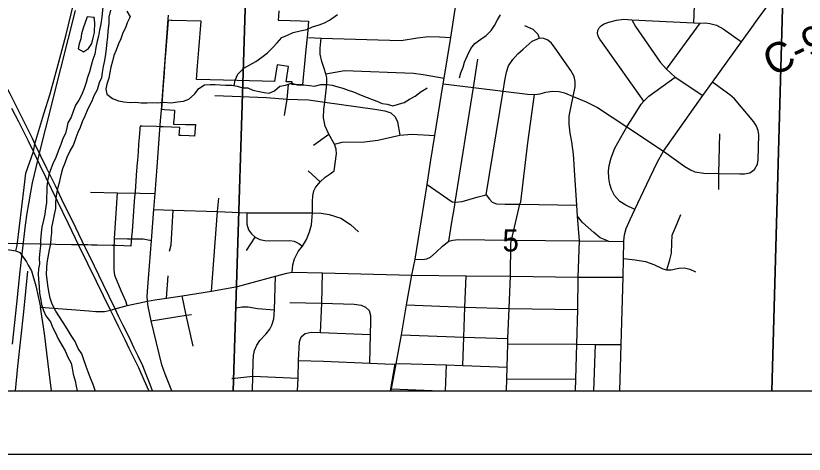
# Model space of a CAD drawing. Extents: x 0 to 34, y 0 to 22.
# Drawn here: x 3.672 to 5.169, y 14 to 14.832 of the extents above; entities that cross this region are included whole.
import ezdxf

# ---------------------------------------------------------------- set-up
doc = ezdxf.new("R2010")
doc.units = 0
for name, color, linetype in [('GM_X_City_Street', 7, 'Continuous'), ('GM_X_Corporation', 7, 'Continuous'), ('GM_X_County_Road', 7, 'Continuous'), ('GM_X_County_Road_Text', 7, 'Continuous'), ('GM_X_Major_River', 7, 'Continuous'), ('GM_X_Minor_Lake', 7, 'Continuous'), ('GM_X_Minor_River', 7, 'Continuous'), ('GM_X_Rail_Line', 7, 'Continuous'), ('GM_X_Section_Text', 7, 'Continuous'), ('GM_X_State_Route', 7, 'Continuous'), ('GM_X_Township_Road', 7, 'Continuous'), ('SH_Data', 7, 'Continuous')]:
    doc.layers.add(name, color=color, linetype=linetype)

msp = doc.modelspace()

# ---------------------------------------------------------------- linework, layer by layer
at = {"layer": 'GM_X_City_Street'}
for p, q in [((4.9075, 14.7307), (4.9715, 14.8177)), ((4.2372, 14.5865), (4.2662, 14.6072)), ((4.2274, 14.5376), (4.25, 14.517)), ((3.9083, 14.4952), (3.9365, 14.4945)), ((4.11, 14.3863), (4.1265, 14.4121)), ((3.9584, 14.2959), (3.9613, 14.3388)), ((4.2508, 14.2308), (4.3456, 14.2274)), ((4.7698, 14.1204), (4.7725, 14.2085)), ((4.4878, 14.1204), (4.4895, 14.1694)), ((4.6045, 14.1431), (4.7352, 14.1422)), ((4.3855, 14.1241), (4.4787, 14.1204))]:
    msp.add_line(p, q, dxfattribs=at)
for points in [[(4.9593, 14.8182), (4.9617, 14.8842), (4.9629, 14.9171), (4.9647, 14.9512)], [(4.7769, 14.8042), (4.7796, 14.8087), (4.7839, 14.8132), (4.7889, 14.8163), (4.798, 14.82), (4.8124, 14.8233), (4.8264, 14.8252), (4.8414, 14.8244), (4.9593, 14.8182), (4.9715, 14.8177), (4.9816, 14.8184), (4.9899, 14.8175), (5.0026, 14.8142), (5.0151, 14.8073), (5.0497, 14.7822)], [(4.8414, 14.8244), (4.8485, 14.8114), (4.8955, 14.7439), (4.9075, 14.7307), (4.9239, 14.7154), (4.9766, 14.6804)], [(4.6381, 14.8133), (4.6535, 14.8065), (4.6631, 14.797), (4.6658, 14.7895)], [(4.228, 14.7907), (4.2521, 14.7892), (4.4038, 14.7851), (4.4349, 14.7898), (4.4556, 14.7923), (4.4762, 14.7919), (4.4978, 14.7908)], [(4.8647, 14.67), (4.7889, 14.7762), (4.781, 14.7876), (4.7776, 14.7934), (4.7762, 14.7986), (4.7769, 14.8042)], [(4.2766, 14.5375), (4.2811, 14.57), (4.2806, 14.5786), (4.2774, 14.5884), (4.2662, 14.6072), (4.2597, 14.6222), (4.2562, 14.6382), (4.2569, 14.6549), (4.2586, 14.6679), (4.2625, 14.7024), (4.2625, 14.7139), (4.2609, 14.722), (4.2578, 14.732), (4.2528, 14.7453), (4.2501, 14.7589), (4.2501, 14.7706), (4.2521, 14.7892)], [(4.565, 14.4919), (4.5975, 14.6889), (4.6006, 14.7089), (4.6037, 14.7249), (4.6078, 14.737), (4.6159, 14.7489), (4.6253, 14.7598), (4.6353, 14.7686), (4.6525, 14.7835), (4.6658, 14.7895)], [(4.7347, 14.1204), (4.7352, 14.1422), (4.7374, 14.209), (4.739, 14.2747), (4.74, 14.3362), (4.7421, 14.4049), (4.7387, 14.4516), (4.7374, 14.4723), (4.7337, 14.5292), (4.731, 14.5695), (4.7277, 14.5926), (4.7246, 14.6093), (4.7224, 14.6262), (4.7224, 14.6411), (4.7262, 14.6602), (4.7304, 14.6784), (4.734, 14.6973), (4.7342, 14.7072), (4.7321, 14.7169), (4.7259, 14.7283), (4.6963, 14.7704), (4.6889, 14.78), (4.6823, 14.7856), (4.6748, 14.7885), (4.6658, 14.7895)], [(4.5048, 14.4689), (4.5063, 14.4781), (4.5413, 14.6958), (4.5495, 14.7495)], [(4.2609, 14.722), (4.296, 14.7278), (4.4273, 14.7228), (4.4455, 14.7202), (4.4851, 14.7132)], [(4.8474, 14.4644), (4.83, 14.4724), (4.8188, 14.4796), (4.8088, 14.4909), (4.8033, 14.502), (4.8001, 14.5123), (4.798, 14.5241), (4.7976, 14.5372), (4.7986, 14.5478), (4.8024, 14.5623), (4.8094, 14.581), (4.8324, 14.6211), (4.8451, 14.6409), (4.8592, 14.6639), (4.8647, 14.67), (4.8741, 14.6791), (4.9239, 14.7154)], [(4.1823, 14.6428), (4.187, 14.6738), (4.1899, 14.7015)], [(4.4835, 14.7027), (4.5413, 14.6958), (4.5975, 14.6889), (4.6435, 14.6831), (4.6568, 14.6827), (4.6667, 14.6836), (4.6785, 14.6868), (4.6912, 14.6886), (4.7035, 14.6884), (4.714, 14.6858), (4.7304, 14.6784), (4.7551, 14.6686), (4.7766, 14.6581), (4.8324, 14.6211), (4.9019, 14.575)], [(4.9019, 14.575), (4.9425, 14.5459), (4.9528, 14.5394), (4.9615, 14.5356), (4.9781, 14.5332), (5.0071, 14.5327), (5.0468, 14.532), (5.0555, 14.5317), (5.0656, 14.5338), (5.0747, 14.5405), (5.0803, 14.5505), (5.0812, 14.5588), (5.0826, 14.6058), (5.0817, 14.6141), (5.0784, 14.6225), (5.0732, 14.6304), (5.0365, 14.674), (5.0279, 14.6818), (5.0091, 14.695), (4.9945, 14.7056)], [(4.0501, 14.6803), (4.148, 14.6767), (4.187, 14.6738), (4.2277, 14.6724), (4.2586, 14.6679), (4.3539, 14.6545), (4.3725, 14.6518), (4.3839, 14.6478), (4.3926, 14.6404), (4.3966, 14.6308), (4.4009, 14.6054)], [(4.6034, 14.1204), (4.6045, 14.1431), (4.6051, 14.1652), (4.606, 14.2098), (4.6063, 14.2197), (4.6088, 14.2764), (4.611, 14.3378), (4.6122, 14.4002), (4.6131, 14.4062), (4.6292, 14.4742), (4.6307, 14.4791), (4.6444, 14.5911), (4.6568, 14.6827)], [(4.2774, 14.5884), (4.2914, 14.5922), (4.3341, 14.5927), (4.3594, 14.5958), (4.4009, 14.6054), (4.4238, 14.6074), (4.4678, 14.605)], [(5.0067, 14.5026), (5.0071, 14.5327), (5.0088, 14.6082)], [(4.1967, 14.3453), (4.198, 14.3591), (4.2011, 14.3706), (4.2083, 14.3847), (4.2165, 14.3949), (4.2237, 14.4073), (4.2299, 14.4219), (4.2334, 14.4352), (4.2351, 14.4578), (4.2354, 14.4792), (4.236, 14.49), (4.2381, 14.4995), (4.2413, 14.5059), (4.25, 14.517), (4.2597, 14.5254), (4.2691, 14.5317), (4.2766, 14.5375)], [(4.4529, 14.5117), (4.5006, 14.4789), (4.5063, 14.4781), (4.5193, 14.4797), (4.5502, 14.4882), (4.565, 14.4919), (4.5715, 14.4841), (4.5765, 14.4781), (4.5848, 14.4749), (4.6012, 14.4742), (4.6292, 14.4742), (4.7374, 14.4723)], [(4.0437, 14.3097), (4.055, 14.4605), (4.0574, 14.4859)], [(3.934, 14.4641), (3.9711, 14.463), (4.055, 14.4605), (4.1106, 14.4583), (4.2351, 14.4578), (4.2521, 14.4574), (4.2671, 14.4549), (4.2891, 14.4476), (4.3076, 14.4361), (4.3229, 14.4221)], [(3.964, 14.385), (3.9669, 14.3974), (3.9711, 14.463)], [(4.43, 14.37), (4.4439, 14.3698), (4.4524, 14.3707), (4.4595, 14.3738), (4.47, 14.3834), (4.4821, 14.3947), (4.4945, 14.4041), (4.5002, 14.4402), (4.5048, 14.4689)], [(4.1106, 14.4583), (4.1106, 14.4367), (4.1137, 14.426), (4.1194, 14.4179), (4.1265, 14.4121), (4.1355, 14.4075), (4.1452, 14.4056), (4.154, 14.4051), (4.1922, 14.4053), (4.2007, 14.4041), (4.2093, 14.3998), (4.2165, 14.3949)], [(4.7971, 14.4043), (4.7816, 14.4105), (4.7694, 14.4207), (4.7479, 14.4397), (4.7387, 14.4516)], [(4.9083, 14.3498), (4.9139, 14.3688), (4.9167, 14.3813), (4.9174, 14.4003), (4.9184, 14.4157), (4.9279, 14.4375), (4.9346, 14.4547)], [(3.8839, 14.4089), (3.8992, 14.409), (3.9141, 14.4084), (3.9296, 14.4054)], [(4.4945, 14.4041), (4.5018, 14.4064), (4.5122, 14.4073), (4.6131, 14.4062), (4.7421, 14.4049), (4.7971, 14.4043), (4.8264, 14.4038)], [(3.8833, 14.2823), (3.8812, 14.2905), (3.8724, 14.3099), (3.8598, 14.3389), (3.8586, 14.3497), (3.8587, 14.3715), (3.8587, 14.3889)], [(4.8257, 14.3711), (4.8482, 14.3689), (4.8673, 14.366), (4.8836, 14.3603), (4.9003, 14.3516), (4.9074, 14.35)], [(4.207, 14.1204), (4.2079, 14.1445), (4.2091, 14.1777), (4.2108, 14.2136), (4.2137, 14.2225), (4.2217, 14.2293), (4.2331, 14.2318), (4.2508, 14.2308), (4.2532, 14.2865), (4.2544, 14.3439)], [(4.9074, 14.35), (4.9083, 14.3498), (4.9163, 14.3497), (4.9309, 14.3532), (4.9414, 14.3535), (4.9516, 14.3511), (4.9625, 14.3461)], [(4.1212, 14.1204), (4.122, 14.1479), (4.1229, 14.1752), (4.1235, 14.1872), (4.1253, 14.1966), (4.1299, 14.2067), (4.1356, 14.216), (4.1476, 14.2286), (4.1543, 14.2375), (4.1582, 14.2451), (4.1619, 14.2568), (4.1634, 14.2739), (4.1652, 14.3381)], [(4.5208, 14.1682), (4.5228, 14.2223), (4.5249, 14.2793), (4.5269, 14.3387)], [(4.0088, 14.2048), (3.9955, 14.2638), (3.9877, 14.3007)], [(4.1926, 14.288), (4.2532, 14.2865), (4.3148, 14.2846), (4.3276, 14.2829), (4.3363, 14.279), (4.3434, 14.272)], [(4.4141, 14.2835), (4.5249, 14.2793), (4.6088, 14.2764), (4.739, 14.2747)], [(3.7399, 14.1204), (3.7335, 14.1715), (3.7263, 14.229), (3.7187, 14.2791)], [(4.0896, 14.2778), (4.1021, 14.2794), (4.1134, 14.2794), (4.1308, 14.2768), (4.1634, 14.2739)], [(4.3442, 14.1726), (4.3456, 14.2274), (4.3463, 14.2519), (4.3463, 14.2625), (4.3434, 14.272)], [(3.9292, 14.2534), (3.9955, 14.2638), (4.0055, 14.2652)], [(4.4043, 14.2266), (4.5228, 14.2223), (4.6063, 14.2197)], [(4.606, 14.2098), (4.7374, 14.209), (4.7725, 14.2085), (4.8213, 14.208)], [(4.2091, 14.1777), (4.2561, 14.1767), (4.3442, 14.1726), (4.3871, 14.171), (4.3943, 14.1713), (4.4005, 14.1723), (4.4895, 14.1694), (4.5208, 14.1682), (4.6051, 14.1652)], [(4.0825, 14.1439), (4.122, 14.1479), (4.2079, 14.1445)]]:
    msp.add_lwpolyline(points, dxfattribs=at)
at = {"layer": 'GM_X_Corporation'}
for points in [[(7.1023, 20.9204), (2.837, 20.9204), (2.837, 14.1204), (9.637, 14.1204), (9.637, 20.9204), (9.4036, 20.9204), (9.4022, 20.8667), (9.2273, 20.8723), (9.1354, 20.8749), (9.124, 20.8753), (8.9858, 20.878), (8.9676, 20.8785), (8.8663, 20.881), (8.6259, 20.8892), (8.5535, 20.8914), (8.5421, 20.8915), (8.4667, 20.8934), (8.0602, 20.9055), (7.9522, 20.9084), (7.1104, 20.9188)], [(3.0463, 14.1204), (4.0849, 14.1204), (4.1106, 14.9455), (3.0765, 14.9841)], [(4.0849, 14.1204), (5.1073, 14.1204), (5.1298, 14.9148), (4.1106, 14.9455)], [(5.1073, 14.1204), (6.1556, 14.1204), (6.1854, 14.88), (5.1298, 14.9148)]]:
    msp.add_lwpolyline(points, close=True, dxfattribs=at)
for points in [[(4.1717, 14.8414), (4.1707, 14.8309), (4.17, 14.8234), (4.1927, 14.8227), (4.2123, 14.8222), (4.2279, 14.8217), (4.2256, 14.7971), (4.225, 14.7915), (4.2245, 14.7858), (4.2221, 14.7614), (4.2201, 14.7405), (4.2182, 14.7216), (4.2162, 14.7009), (4.1962, 14.7015), (4.1969, 14.7064), (4.1855, 14.7067), (4.1896, 14.7357), (4.168, 14.7389), (4.1633, 14.7073), (4.0925, 14.7092), (4.0153, 14.7112), (4.0173, 14.737), (4.0196, 14.7672), (4.0238, 14.8214), (3.9688, 14.823), (3.9681, 14.8231), (3.967, 14.8231), (3.9613, 14.8233), (3.957, 14.7675), (3.9559, 14.7533), (3.9547, 14.737), (3.9536, 14.7228), (3.9525, 14.7087), (3.9505, 14.6834), (3.9505, 14.6826), (3.9484, 14.6548), (3.9483, 14.6544), (3.9546, 14.6539), (3.9734, 14.6525), (3.9733, 14.6509), (3.9726, 14.6414), (3.9718, 14.632), (3.9717, 14.6307), (3.9714, 14.6263), (3.9941, 14.6258), (4.0131, 14.6253), (4.0114, 14.6037), (4.0014, 14.6041), (3.9859, 14.6046), (3.9825, 14.6047), (3.9837, 14.6202), (3.952, 14.6212), (3.9458, 14.6214), (3.9395, 14.6216), (3.9117, 14.6226), (3.9079, 14.6227), (3.9076, 14.6193), (3.9074, 14.6165), (3.9062, 14.6008), (3.9053, 14.5885), (3.9041, 14.5733), (3.903, 14.5582), (3.9021, 14.5465), (3.902, 14.5455), (3.9008, 14.5295), (3.9007, 14.5283), (3.9, 14.5189), (3.8984, 14.4978), (3.8981, 14.494), (3.8971, 14.4801), (3.8964, 14.4705), (3.8956, 14.461), (3.8949, 14.4515), (3.8942, 14.442), (3.8935, 14.4325), (3.8928, 14.423), (3.892, 14.4128), (3.8917, 14.409), (3.8914, 14.4052), (3.8906, 14.3949), (3.8773, 14.3953), (3.8629, 14.3958), (3.8591, 14.3959), (3.8553, 14.396), (3.8268, 14.3968), (3.8256, 14.3969), (3.8235, 14.3969), (3.8159, 14.397), (3.8091, 14.3971), (3.797, 14.3973), (3.7868, 14.3972), (3.7781, 14.3976), (3.6263, 14.4007)], [(3.0474, 14.1204), (9.2101, 14.1204)], [(3.4295, 14.1204), (5.4145, 14.1204)]]:
    msp.add_lwpolyline(points, dxfattribs=at)
at = {"layer": 'GM_X_County_Road'}
for points in [[(4.1141, 14.324), (4.1652, 14.3381), (4.1869, 14.3437), (4.1967, 14.3453), (4.2544, 14.3439), (4.4238, 14.3398)], [(4.4238, 14.3398), (4.5269, 14.3387), (4.611, 14.3378), (4.74, 14.3362), (4.8253, 14.3358)], [(3.9221, 14.2907), (3.9363, 14.2927), (3.9584, 14.2959), (3.9877, 14.3007), (4.0437, 14.3097), (4.0932, 14.3183), (4.1141, 14.324)], [(3.8608, 14.276), (3.8833, 14.2823), (3.9221, 14.2907)], [(3.9684, 14.1204), (3.9558, 14.1518), (3.9496, 14.1699), (3.9394, 14.2113), (3.9292, 14.2534), (3.9231, 14.2801), (3.9221, 14.2907)], [(3.7187, 14.2791), (3.7943, 14.2733), (3.8108, 14.272)], [(3.8108, 14.272), (3.8242, 14.2709), (3.8407, 14.2709), (3.8516, 14.2732), (3.8608, 14.276)]]:
    msp.add_lwpolyline(points, dxfattribs=at)
at = {"layer": 'GM_X_Major_River'}
for points in [[(3.8374, 14.8489), (3.8353, 14.8292), (3.8334, 14.8167), (3.8312, 14.8045), (3.8294, 14.7931), (3.8267, 14.7836), (3.8241, 14.7718), (3.8219, 14.7593), (3.8182, 14.7487), (3.8152, 14.7376), (3.8122, 14.7255), (3.8085, 14.7148), (3.8059, 14.7053), (3.8018, 14.6936), (3.7969, 14.6814), (3.7916, 14.6719), (3.7856, 14.662), (3.7811, 14.6502), (3.777, 14.6396), (3.771, 14.6289), (3.7687, 14.619), (3.7665, 14.6088), (3.7612, 14.5989), (3.7575, 14.5879), (3.7523, 14.5749), (3.7478, 14.5631), (3.7421, 14.551), (3.738, 14.5396), (3.7346, 14.5301), (3.7324, 14.5183), (3.7313, 14.5073), (3.731, 14.4978), (3.7303, 14.4879), (3.7303, 14.4773), (3.7285, 14.4663), (3.7274, 14.4556), (3.7248, 14.4442), (3.7218, 14.4306), (3.72, 14.4199), (3.7189, 14.4059), (3.719, 14.3956), (3.7175, 14.3854), (3.7164, 14.3721), (3.7168, 14.3615), (3.7154, 14.352), (3.7147, 14.3417), (3.7151, 14.3322), (3.7163, 14.3178), (3.7171, 14.3057), (3.719, 14.2962), (3.7206, 14.2844), (3.7248, 14.273), (3.7291, 14.2628), (3.7382, 14.2511), (3.7417, 14.2412), (3.7474, 14.2302), (3.7528, 14.2189), (3.7596, 14.2071), (3.7658, 14.1961), (3.7711, 14.184), (3.7769, 14.1726), (3.7788, 14.1632), (3.7811, 14.1522), (3.785, 14.1393), (3.7865, 14.129), (3.7889, 14.1204)], [(3.8313, 14.705), (3.8354, 14.7149), (3.8369, 14.7244), (3.8387, 14.7358), (3.8409, 14.7472), (3.8428, 14.759), (3.8443, 14.7696), (3.8457, 14.7818), (3.8468, 14.792), (3.8475, 14.8027), (3.8493, 14.8171), (3.8493, 14.8289), (3.8523, 14.8422)], [(3.8234, 14.1204), (3.823, 14.1212), (3.8191, 14.1322), (3.8138, 14.1443), (3.8095, 14.1564), (3.8057, 14.1667), (3.8003, 14.1811), (3.7973, 14.1906), (3.7908, 14.2004), (3.785, 14.2137), (3.777, 14.2254), (3.7697, 14.2379), (3.7617, 14.25), (3.7548, 14.2606), (3.7483, 14.2716), (3.7411, 14.2845), (3.7376, 14.2959), (3.7345, 14.3091), (3.733, 14.3209), (3.7306, 14.3414), (3.7309, 14.3535), (3.7316, 14.363), (3.7335, 14.3737), (3.7361, 14.3877), (3.7383, 14.3991), (3.7394, 14.4101), (3.7405, 14.4204), (3.7408, 14.4303), (3.743, 14.4424), (3.7456, 14.4549), (3.7478, 14.466), (3.7482, 14.4755), (3.7489, 14.4865), (3.7503, 14.4971), (3.7526, 14.507), (3.7556, 14.5184), (3.7582, 14.5298), (3.7615, 14.5419), (3.766, 14.553), (3.7694, 14.5636), (3.7746, 14.5743), (3.7814, 14.5864), (3.7866, 14.6009), (3.7908, 14.6111), (3.7949, 14.6206), (3.7986, 14.6313), (3.8039, 14.6419), (3.8095, 14.656), (3.817, 14.6708), (3.8208, 14.6803), (3.8272, 14.6921), (3.8313, 14.705)]]:
    msp.add_lwpolyline(points, dxfattribs=at)
at = {"layer": 'GM_X_Minor_Lake'}
for points in [[(3.8076, 14.8298), (3.8038, 14.8188), (3.8001, 14.8082), (3.7971, 14.7979), (3.7953, 14.788), (3.7926, 14.7785), (3.7908, 14.7691), (3.8003, 14.7634), (3.8101, 14.7695), (3.8162, 14.779), (3.8191, 14.7897), (3.8217, 14.7999), (3.8224, 14.8189), (3.8209, 14.8288)], [(3.8076, 14.8298), (3.8038, 14.8188), (3.8001, 14.8082), (3.7971, 14.7979), (3.7953, 14.788), (3.7926, 14.7785), (3.7908, 14.7691), (3.8003, 14.7634), (3.8101, 14.7695), (3.8162, 14.779), (3.8191, 14.7897), (3.8217, 14.7999), (3.8224, 14.8189), (3.8209, 14.8288), (3.8212, 14.828)], [(3.8209, 14.8288), (3.8076, 14.8298)]]:
    msp.add_lwpolyline(points, dxfattribs=at)
at = {"layer": 'GM_X_Minor_River'}
for points in [[(3.883, 14.8404), (3.8891, 14.8298), (3.8838, 14.8187), (3.8805, 14.8092), (3.8756, 14.7994), (3.8715, 14.788), (3.8673, 14.7784), (3.8628, 14.7667), (3.8583, 14.7564), (3.8557, 14.7458), (3.8528, 14.7344), (3.8509, 14.7241), (3.8487, 14.7135), (3.8449, 14.7024), (3.8431, 14.6929), (3.845, 14.6831), (3.8557, 14.6748), (3.8671, 14.6706), (3.8773, 14.6684), (3.8895, 14.6673), (3.8997, 14.6677), (3.9099, 14.667), (3.9217, 14.667), (3.9312, 14.6675), (3.941, 14.6664), (3.9528, 14.6679), (3.9672, 14.6665), (3.9793, 14.6684), (3.9907, 14.6696), (4.0009, 14.6738), (4.0115, 14.6829), (4.0194, 14.6936), (4.0304, 14.7009), (4.041, 14.7016), (4.0505, 14.7013), (4.0599, 14.7006), (4.0702, 14.7002), (4.0823, 14.6999), (4.0926, 14.6984), (4.1032, 14.695), (4.1127, 14.6951), (4.1222, 14.6906), (4.1339, 14.6883), (4.1438, 14.6865), (4.1533, 14.685), (4.1631, 14.6896), (4.1733, 14.698), (4.1839, 14.7003), (4.1957, 14.7037), (4.2067, 14.7011), (4.2188, 14.7008), (4.2298, 14.6997), (4.2393, 14.6982), (4.251, 14.7013), (4.2624, 14.7013), (4.273, 14.6999), (4.2837, 14.6969), (4.2932, 14.6946), (4.303, 14.6909), (4.3133, 14.6875), (4.3232, 14.6833), (4.3338, 14.6788), (4.3574, 14.6698), (4.3676, 14.6657), (4.3771, 14.6642), (4.3881, 14.6612), (4.4093, 14.6673), (4.4195, 14.6738), (4.4301, 14.6796), (4.4418, 14.688), (4.4524, 14.6948), (4.4532, 14.6952)], [(4.0867, 14.6993), (4.0883, 14.7094), (4.0936, 14.7212), (4.1053, 14.7323), (4.1166, 14.7388), (4.1276, 14.7452), (4.1393, 14.7536), (4.1499, 14.7613), (4.1597, 14.7712), (4.168, 14.7807), (4.1771, 14.7906), (4.188, 14.7952), (4.1986, 14.7998), (4.2119, 14.8033), (4.2248, 14.806), (4.2354, 14.8106), (4.2479, 14.8144), (4.2581, 14.8182), (4.2679, 14.8232), (4.283, 14.8343)], [(4.5145, 14.714), (4.5171, 14.7235), (4.5216, 14.7346), (4.5242, 14.7441), (4.5295, 14.7566), (4.5359, 14.7695), (4.5438, 14.7794), (4.5547, 14.7875), (4.5653, 14.7943), (4.5748, 14.8039), (4.5808, 14.8134), (4.5864, 14.8244), (4.5924, 14.8339)]]:
    msp.add_lwpolyline(points, dxfattribs=at)
at = {"layer": 'GM_X_Rail_Line'}
msp.add_line((4.3836, 14.1204), (4.3923, 14.1714), dxfattribs=at)
for points in [[(3.6657, 14.2089), (3.6741, 14.2851), (3.6806, 14.3473), (3.6904, 14.4346), (3.6935, 14.4574), (3.6967, 14.475), (3.7005, 14.4974), (3.7037, 14.5151), (3.7074, 14.531), (3.7198, 14.5814), (3.7292, 14.6188), (3.7575, 14.7317), (3.7856, 14.8419)], [(3.6944, 14.3472), (3.6867, 14.2704), (3.6753, 14.1667), (3.6706, 14.1204)]]:
    msp.add_lwpolyline(points, dxfattribs=at)
at = {"layer": 'GM_X_State_Route'}
for points in [[(4.8265, 14.4047), (4.8279, 14.4162), (4.831, 14.4284), (4.8385, 14.4455), (4.8474, 14.4644), (4.8702, 14.5127), (4.8895, 14.5535), (4.9019, 14.575), (4.9766, 14.6804), (4.9945, 14.7056), (5.0497, 14.7822), (5.0662, 14.805), (5.0802, 14.8247), (5.096, 14.8462), (5.1106, 14.8677), (5.1144, 14.8734)], [(3.9493, 14.6623), (3.961, 14.8169), (3.9622, 14.8333)], [(3.7036, 14.599), (3.6918, 14.6231), (3.6786, 14.6499), (3.6612, 14.6838), (3.6477, 14.7095), (3.6329, 14.7338), (3.6232, 14.7493), (3.6071, 14.7728), (3.5888, 14.7972), (3.5767, 14.8127)], [(3.8516, 14.2732), (3.8255, 14.3279), (3.8089, 14.3614), (3.7918, 14.3963), (3.7719, 14.4371), (3.7512, 14.4804), (3.7176, 14.5491), (3.7055, 14.5741), (3.6959, 14.5939), (3.6776, 14.6305), (3.6645, 14.6559)], [(3.947, 14.6324), (3.9492, 14.6603), (3.9493, 14.6623)], [(3.9221, 14.2907), (3.9217, 14.2998), (3.9228, 14.3173), (3.9241, 14.3336), (3.9296, 14.4054), (3.934, 14.4641), (3.9365, 14.4945), (3.9402, 14.5452), (3.9456, 14.6155), (3.947, 14.6324)], [(3.7472, 14.5092), (3.7313, 14.542), (3.7084, 14.5892), (3.7036, 14.599)], [(3.7733, 14.4556), (3.7635, 14.4754), (3.7472, 14.5092)], [(3.8039, 14.3924), (3.7862, 14.4295), (3.7733, 14.4556)], [(4.8253, 14.3358), (4.8257, 14.3711), (4.8264, 14.4038), (4.8265, 14.4047)], [(3.8216, 14.3568), (3.8043, 14.3915), (3.8039, 14.3924)], [(3.8608, 14.276), (3.8379, 14.3228), (3.8216, 14.3568)], [(4.8186, 14.1204), (4.8213, 14.208), (4.8253, 14.3358)], [(3.8608, 14.276), (3.8833, 14.2823), (3.9221, 14.2907)], [(3.9249, 14.1204), (3.9247, 14.121), (3.916, 14.1409), (3.9054, 14.1638), (3.8963, 14.1829), (3.8874, 14.2006), (3.8795, 14.2171), (3.8676, 14.2412), (3.8592, 14.258), (3.8516, 14.2732)], [(3.9314, 14.1204), (3.927, 14.1327), (3.9198, 14.1516), (3.913, 14.1675), (3.9043, 14.1861), (3.897, 14.2016), (3.887, 14.2221), (3.876, 14.2444), (3.8677, 14.261), (3.8608, 14.276)]]:
    msp.add_lwpolyline(points, dxfattribs=at)
at = {"layer": 'GM_X_Township_Road'}
msp.add_line((3.8595, 14.4092), (3.8839, 14.4089), dxfattribs=at)
for points in [[(3.743, 14.7047), (3.7526, 14.7397), (3.7674, 14.7965), (3.7815, 14.8536), (3.7886, 14.8851), (3.7945, 14.9196), (3.7998, 14.9546), (3.8016, 14.9654)], [(4.4596, 14.5539), (4.4678, 14.605), (4.4835, 14.7027), (4.4851, 14.7132), (4.4978, 14.7908), (4.5063, 14.8443), (4.5121, 14.8788), (4.5145, 14.8897), (4.5166, 14.8968), (4.5228, 14.9156), (4.5299, 14.9317), (4.5346, 14.9402)], [(3.6723, 14.3861), (3.6749, 14.3963), (3.6877, 14.5063), (3.6914, 14.5333), (3.7055, 14.5741), (3.7084, 14.5892), (3.7251, 14.6461), (3.7373, 14.6838), (3.743, 14.7047)], [(4.4238, 14.3398), (4.43, 14.37), (4.4529, 14.5117), (4.4596, 14.5539)], [(3.8138, 14.4971), (3.865, 14.4959), (3.9083, 14.4952)], [(3.8587, 14.3889), (3.8595, 14.4092), (3.865, 14.4959)], [(3.6149, 14.3969), (3.6339, 14.3931), (3.6528, 14.3893), (3.6723, 14.3861), (3.6798, 14.3831), (3.6922, 14.3648), (3.6955, 14.3589)], [(3.6955, 14.3589), (3.7016, 14.3479), (3.7103, 14.3198), (3.7187, 14.2791)], [(4.3848, 14.1204), (4.3855, 14.1241), (4.3943, 14.1713), (4.4043, 14.2266), (4.4141, 14.2835), (4.4238, 14.3398)]]:
    msp.add_lwpolyline(points, dxfattribs=at)
at = {"layer": 'SH_Data'}
msp.add_line((2.7349, 14.0001), (9.7349, 14.0001), dxfattribs=at)

# ---------------------------------------------------------------- texts
at = {"layer": 'GM_X_County_Road_Text'}
msp.add_text('C-98', height=0.05682, rotation=24.87, dxfattribs=at).set_placement((5.1077, 14.7157))
at = {"layer": 'GM_X_Section_Text'}
msp.add_text('5', height=0.0419, rotation=0, dxfattribs=at).set_placement((4.5961, 14.3847))

doc.saveas('drawing.dxf')
